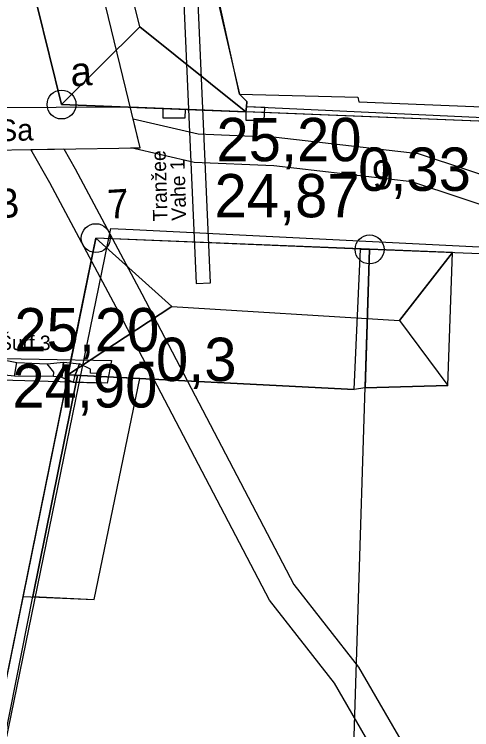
# Model space of a CAD drawing. Extents: x 738423 to 738903, y 6589762 to 6590172.
# Drawn here: x 738705.18 to 738736.84, y 6589904.84 to 6589954.37 of the extents above; entities that cross this region are included whole.
import ezdxf

# ---------------------------------------------------------------- set-up
doc = ezdxf.new("R2010")
doc.units = 0
for name, color, linetype in [('_1927_hoonestus', 7, 'Continuous'), ('_1927_katuse_kalded', 7, 'Continuous'), ('_1927_koordin_punktid_nr', 7, 'Continuous'), ('_1927_krundi_piir', 7, 'Continuous'), ('_1927_uhepoolne_katusekalle', 7, 'Continuous'), ('_a_ajalooline_maapind', 7, 'Continuous'), ('_a_olol_maapind', 7, 'Continuous'), ('_ajalooline_kalmistu', 7, 'Continuous'), ('_ajalooline_liivavall_linnamuur', 7, 'Continuous'), ('_arheol_Raamatukogu_tekst', 7, 'Continuous'), ('_arheol_Raamatukogu_tranžee', 7, 'Continuous'), ('_arheol_Suur10c_kõnnitee_plaadid', 7, 'Continuous'), ('_arheol_Suur10c_müür', 7, 'Continuous'), ('_arheol_Suur10c_sõidutee', 7, 'Continuous'), ('_arheol_Suur10c_tranžee', 7, 'Continuous'), ('a_dendro_puu_nr', 7, 'Continuous'), ('ARHEO', 7, 'Continuous'), ('plan_ala', 7, 'Continuous'), ('v_olol_kitsendus_tehnov', 7, 'Continuous')]:
    doc.layers.add(name, color=color, linetype=linetype)

msp = doc.modelspace()

# ---------------------------------------------------------------- linework, layer by layer
at = {"layer": '_1927_hoonestus'}
for points in [[(738720.769, 6589948.828), (738717.391, 6589964.21), (738744.328, 6589967.017), (738743.287, 6589975.86), (738743.781, 6589976.591), (738742.788, 6589981.892), (738731.64, 6589980.716), (738731.591, 6589981.177), (738730.837, 6589981.808), (738729.788, 6589981.705), (738728.975, 6589980.706), (738729.211, 6589978.131), (738723.254, 6589977.196), (738722.667, 6589980.94), (738713.453, 6589980.351), (738702.451, 6589977.869), (738702.372, 6589978.216), (738701.084, 6589977.902), (738708.45, 6589948.12), (738721.212, 6589947.611), (738721.255, 6589947.963), (738721.272, 6589948.32)], [(738721.212, 6589947.611), (738721.212, 6589947.038), (738722.476, 6589947.038), (738722.517, 6589947.904), (738721.255, 6589947.959)], [(738715.452, 6589947.841), (738715.452, 6589947.205), (738717.017, 6589947.205), (738717.038, 6589947.777)], [(738710.819, 6589938.87), (738708.889, 6589929.394), (738728.695, 6589928.399), (738729.135, 6589938.114)], [(738729.135, 6589938.114), (738729.77, 6589938.088), (738729.464, 6589928.5), (738728.695, 6589928.399)], [(738729.77, 6589938.088), (738729.464, 6589928.5), (738735.177, 6589928.662), (738735.5, 6589937.866)], [(738709.555, 6589929.361), (738708.889, 6589929.394), (738701.805, 6589894.604), (738702.574, 6589894.447), (738706.455, 6589914.049)], [(738713.861, 6589929.144), (738709.555, 6589929.361), (738706.455, 6589914.049), (738710.703, 6589913.85)]]:
    msp.add_lwpolyline(points, close=True, dxfattribs=at)
msp.add_lwpolyline([(738760.417, 6589979.761), (738760.417, 6589979.761), (738758.219, 6589948.155), (738756.018, 6589946.345), (738721.255, 6589947.963), (738721.272, 6589948.32), (738720.769, 6589948.828), (738728.963, 6589948.63), (738729.025, 6589948.312), (738755.745, 6589947.212), (738757.492, 6589948.655), (738759.702, 6589979.598), (738760.417, 6589979.761)], dxfattribs=at)
at = {"layer": '_1927_katuse_kalded'}
for points in [[(738708.932, 6589973.351), (738713.453, 6589980.351), (738720.769, 6589948.828), (738721.272, 6589948.32), (738721.255, 6589947.959), (738721.212, 6589947.611), (738713.862, 6589953.509)], [(738713.862, 6589953.509), (738708.932, 6589973.351), (738701.164, 6589977.579), (738708.45, 6589948.12)], [(738708.45, 6589948.12), (738713.862, 6589953.509), (738721.212, 6589947.611)], [(738710.819, 6589938.87), (738716.088, 6589934.145), (738708.889, 6589929.394)], [(738710.819, 6589938.87), (738716.088, 6589934.145), (738731.836, 6589933.165), (738735.5, 6589937.866)], [(738735.5, 6589937.866), (738731.836, 6589933.165), (738735.177, 6589928.662)], [(738731.836, 6589933.165), (738735.177, 6589928.662), (738729.464, 6589928.5), (738728.695, 6589928.399), (738708.889, 6589929.394), (738716.088, 6589934.145)]]:
    msp.add_lwpolyline(points, close=True, dxfattribs=at)
at = {"layer": '_1927_koordin_punktid_nr'}
for centre in [(738708.45, 6589948.12), (738710.819, 6589938.87), (738729.77, 6589938.088)]:
    msp.add_circle(centre, 1, dxfattribs=at)
at = {"layer": '_1927_krundi_piir'}
for p in [(738728.17, 6589888.006), (738758.478, 6589936.976)]:
    msp.add_line(p, (738729.77, 6589938.088), dxfattribs=at)
msp.add_lwpolyline([(738708.45, 6589948.12), (738700.042, 6589982.114), (738690.737, 6590019.738), (738730.327, 6590028.224), (738730.742, 6590028.31), (738759.446, 6590034.134), (738761.505, 6589995.407), (738758.078, 6589946.139)], close=True, dxfattribs=at)
msp.add_lwpolyline([(738729.77, 6589938.088), (738710.819, 6589938.87), (738701.034, 6589890.819), (738730.269, 6589887.789)], dxfattribs=at)
at = {"layer": '_1927_uhepoolne_katusekalle'}
msp.add_lwpolyline([(738705.765, 6589914.054), (738710.703, 6589913.85), (738713.861, 6589929.144), (738708.889, 6589929.394)], close=True, dxfattribs=at)
at = {"layer": '_ajalooline_kalmistu'}
msp.add_lwpolyline([(738700.48, 6589884.054), (738711.856, 6589939.535), (738713.397, 6589939.458), (738744.261, 6589937.911), (738742.668, 6589879.491)], close=True, dxfattribs=at)
at = {"layer": '_ajalooline_liivavall_linnamuur'}
msp.add_lwpolyline([(738708.289, 6589968.147), (738780.226, 6589985.561), (738769.668, 6589952.526), (738767.82, 6589945.735), (738713.209, 6589947.93), (738615.937, 6589947.499), (738617.458, 6589962.743), (738623.555, 6589962.32), (738622.897, 6589952.277), (738711.457, 6589955.13)], close=True, dxfattribs=at)
at = {"layer": '_arheol_Raamatukogu_tranžee'}
msp.add_lwpolyline([(738717.761, 6589935.735), (738718.76, 6589935.779), (738716.021, 6589998.219), (738715.022, 6589998.175)], close=True, dxfattribs=at)
at = {"layer": '_arheol_Suur10c_kõnnitee_plaadid'}
msp.add_line((738708.472, 6589929.209), (738708.589, 6589930.278), dxfattribs=at)
msp.add_lwpolyline([(738708.589, 6589930.278), (738708.472, 6589929.209), (738708.589, 6589930.278), (738709.691, 6589930.169), (738709.35, 6589929.277), (738709.265, 6589928.896), (738708.472, 6589929.209)], close=True, dxfattribs=at)
at = {"layer": '_arheol_Suur10c_müür'}
msp.add_line((738709.35, 6589929.277), (738709.691, 6589930.169), dxfattribs=at)
msp.add_lwpolyline([(738709.691, 6589930.169), (738709.35, 6589929.277), (738709.265, 6589928.896), (738711.113, 6589928.847), (738711.204, 6589929.49), (738710.447, 6589929.515), (738710.46, 6589929.807)], close=True, dxfattribs=at)
msp.add_lwpolyline([(738711.204, 6589929.49), (738710.447, 6589929.515), (738710.46, 6589929.807)], dxfattribs=at)
at = {"layer": '_arheol_Suur10c_sõidutee'}
msp.add_lwpolyline([(738703.942, 6589930.547), (738705.357, 6589930.26), (738707.458, 6589930.172), (738708.589, 6589930.278), (738708.472, 6589929.209), (738707.887, 6589929.296), (738705.192, 6589929.31), (738703.758, 6589929.457)], close=True, dxfattribs=at)
at = {"layer": '_arheol_Suur10c_tranžee'}
msp.add_lwpolyline([(738701.794, 6589929.094), (738701.879, 6589930.589), (738711.897, 6589930.387), (738711.607, 6589928.834)], close=True, dxfattribs=at)
at = {"layer": 'ARHEO'}
msp.add_line((738705.192, 6589929.31), (738705.357, 6589930.26), dxfattribs=at)
msp.add_lwpolyline([(738707.887, 6589929.296), (738707.911, 6589929.59), (738707.458, 6589930.172)], dxfattribs=at)
at = {"layer": 'plan_ala'}
msp.add_lwpolyline([(738772.222, 6589837.873), (738583.11, 6589865.67), (738583.11, 6589865.67), (738577.13, 6589865.85), (738565.704, 6589866.139), (738565.45, 6589885.77), (738564.493, 6589941.053), (738581.9, 6589941.15), (738615.11, 6589942.17), (738650.05, 6589943.32), (738691.269, 6589944.8), (738696.09, 6589944.851), (738713.89, 6589945.13), (738703.51, 6589987.79), (738752.88, 6590000.39), (738783.141, 6590007.464), (738767.569, 6589951.88)], close=True, dxfattribs=at)
at = {"layer": 'v_olol_kitsendus_tehnov'}
msp.add_line((738713.89, 6589945.13), (738713.89, 6589945.13), dxfattribs=at)
for points in [[(738713.89, 6589945.13), (738713.402, 6589947.136), (738717.896, 6589946.096), (738723.296, 6589945.869), (738733.125, 6589944.736), (738740.024, 6589942.441), (738745.577, 6589941.347), (738756.146, 6589941.169)], [(738756.882, 6589887.758), (738756.6, 6589887.893), (738753.923, 6589888.407), (738750.047, 6589888.036), (738739.475, 6589888.647), (738737.816, 6589889.811), (738734.733, 6589895.26), (738727.337, 6589908.047), (738722.844, 6589913.793), (738712.24, 6589934.08), (738707.629, 6589942.7), (738706.323, 6589945.015), (738708.6, 6589945.05)], [(738708.6, 6589945.05), (738709.382, 6589943.663), (738714.008, 6589935.015), (738724.532, 6589914.881), (738728.999, 6589909.169), (738736.469, 6589896.254), (738739.334, 6589891.189), (738740.159, 6589890.611), (738750.009, 6589890.041), (738754.019, 6589890.425), (738756.911, 6589889.87)], [(738756.203, 6589939.168), (738745.365, 6589939.351), (738739.514, 6589940.503), (738732.691, 6589942.772), (738723.14, 6589943.873), (738717.626, 6589944.106), (738713.242, 6589945.12), (738713.89, 6589945.13)]]:
    msp.add_lwpolyline(points, dxfattribs=at)

# ---------------------------------------------------------------- texts
at = {"layer": '_1927_koordin_punktid_nr'}
for s, p in [('a', (738709.118, 6589949.373)), ('9', (738730.002, 6589942.216)), ('3', (738704.075, 6589940.25)), ('7', (738711.687, 6589940.207))]:
    msp.add_text(s, height=2, rotation=3.5609, dxfattribs=at).set_placement(p)
at = {"layer": '_a_ajalooline_maapind'}
for s, p in [('-0,33', (738727.639, 6589942.145)), ('24,87', (738719.038, 6589940.31)), ('-0,3', (738713.649, 6589928.977)), ('24,90', (738705.048, 6589927.141))]:
    msp.add_text(s, height=3, dxfattribs=at).set_placement(p)
at = {"layer": '_a_olol_maapind'}
for p in [(738719.173, 6589944.197), (738705.183, 6589931.028)]:
    msp.add_text('25,20', height=3, dxfattribs=at).set_placement(p)
at = {"layer": '_arheol_Raamatukogu_tekst'}
for s, rotation, p in [('Tranžee ', 91.6203, (738715.789, 6589940.06)), ('Vahe 1', 91.6203, (738717.083, 6589940.097)), ('Šurf 3', 359.9929, (738704.125, 6589931.121))]:
    msp.add_text(s, height=1, rotation=rotation, dxfattribs=at).set_placement(p)
at = {"layer": 'a_dendro_puu_nr'}
msp.add_text('233Sa', height=1.5, rotation=1.7381, dxfattribs=at).set_placement((738700.717, 6589945.464))

doc.saveas('drawing.dxf')
